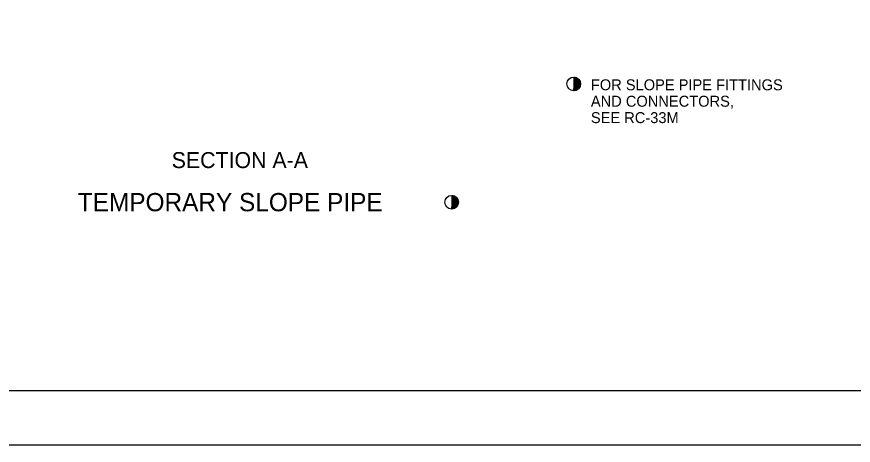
# Model space of a CAD drawing. Extents: x 636462 to 637367, y 299944 to 300538.
# Drawn here: x 636692.5 to 636921.8, y 299944.4 to 300061.7 of the extents above; entities that cross this region are included whole.
import ezdxf

# ---------------------------------------------------------------- set-up
doc = ezdxf.new("R2010")
doc.units = 0
for name, color, linetype in [('1', 7, 'Continuous'), ('Default', 7, 'Continuous'), ('PLT-BNDY', 7, 'Continuous')]:
    doc.layers.add(name, color=color, linetype=linetype)

# ---------------------------------------------------------------- blocks, each defined once
blk = doc.blocks.new('CIR')
at = {"layer": 'Default'}
blk.add_line((0, 0.444), (0, -0.445), dxfattribs=at)
blk.add_lwpolyline([(0.023, -0.425), (0.167, -0.391), (0.27, -0.337), (0.35, -0.237), (0.404, -0.123), (0.419, 0.02), (0.384, 0.154), (0.325, 0.272), (0.241, 0.332), (0.162, 0.396), (0.087, 0.416), (0.028, 0.421), (0.008, -0.416), (0.073, 0.401), (0.067, -0.401), (0.137, 0.401), (0.132, -0.386), (0.186, 0.366), (0.186, -0.366), (0.251, 0.312), (0.256, -0.337), (0.325, 0.258), (0.33, -0.257), (0.389, 0.124), (0.394, -0.123), (0.008, -0.406), (0.33, -0.223), (0.067, -0.223), (0.399, 0.094), (0.038, 0.406), (0.344, 0.069), (0.053, 0.262), (0.29, 0.267), (0.112, 0.391)], dxfattribs=at)
blk.add_circle((0, 0), 0.445, dxfattribs=at)

msp = doc.modelspace()

# ---------------------------------------------------------------- linework, layer by layer
at = {"layer": '1'}
msp.add_lwpolyline([(637287.91, 299959.45), (637287.91, 300523.45), (636501.91, 300523.45), (636501.91, 299959.45), (637287.91, 299959.45), (637287.91, 299985.81), (637087.91, 299985.81), (637087.91, 300050.49), (637287.91, 300050.49), (637287.91, 300079.45), (637087.91, 300079.45), (637087.91, 299959.45), (637166.72, 299959.45), (637166.72, 299985.81), (637166.72, 299959.45), (637243.72, 299959.45), (637243.72, 299985.81), (637243.72, 299973.49), (637287.91, 299973.49)], dxfattribs=at)
at = {"layer": 'PLT-BNDY'}
msp.add_lwpolyline([(636461.91, 300538.45), (637302.91, 300538.45), (637302.91, 299944.45), (636461.91, 299944.45)], close=True, dxfattribs=at)

# ---------------------------------------------------------------- block references
at = {"layer": 'Default', "xscale": 4.229924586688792, "yscale": 4.229924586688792}
for p in [(636845.15, 300043.34), (636811.71, 300010.97)]:
    msp.add_blockref('CIR', p, dxfattribs=at)

# ---------------------------------------------------------------- texts
at = {"layer": 'Default'}
for s, height, p in [('FOR SLOPE PIPE FITTINGS', 2.998, (636849.86, 300041.62)), ('AND CONNECTORS,', 2.998, (636849.86, 300037.12)), ('SEE RC-33M', 2.998, (636849.86, 300032.63)), ('SECTION A-A', 4.3721, (636734.98, 300020.32)), ('TEMPORARY SLOPE PIPE', 4.9967, (636709.26, 300008.5))]:
    msp.add_text(s, height=height, dxfattribs=at).set_placement(p)

doc.saveas('drawing.dxf')
